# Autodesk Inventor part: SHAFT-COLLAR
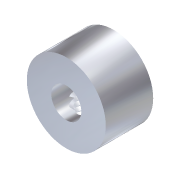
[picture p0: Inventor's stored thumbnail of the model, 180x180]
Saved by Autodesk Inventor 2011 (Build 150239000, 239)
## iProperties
Created: 2007-08
Part Number: SHAFT-COLLAR
Material: Stainless Steel
Document SubType Name: Modeling
Density: 8.08 g/cm^3
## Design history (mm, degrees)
feature "Base1"
body "Solid1"
